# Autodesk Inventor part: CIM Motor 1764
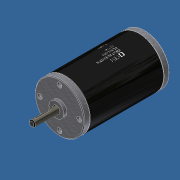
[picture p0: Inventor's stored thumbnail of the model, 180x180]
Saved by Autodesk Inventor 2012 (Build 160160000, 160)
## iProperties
Created: 2008-01
Part Number: CIM Motor 1764
Document SubType Name: Modeling
Designer: gstuder
Density: 1 g/cm^3
Mass: 1474.17 g
Surface Area: 428.563 cm^2
Volume: 334.464 cm^3
Catalog Web Link: ifirobotics.
Description: 2.5" CIM Motor
Material: Default
Author: gstuder
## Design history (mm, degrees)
sketch "Sketch1"
  geometry: L1 (0, 44.45)-(0, -44.45) reference; L2 (-44.45, 0)-(44.45, 0) reference; C1 r 31.75 at (0, 0)
  constraints: 2 midpoint, 1 centre point
  dimensions: "d0" = 63.5 diameter of C1
extrude "Extrusion1" new body sketch "Sketch1" stored distance "d1" = 95.25; taper "d2" = 0 deg
fillet "Fillet1" dims "d3" = 0.635
sketch "Sketch2"
  geometry: C1 r 31.75 at (0, 0) reference; C2 r 31.75 at (0, 0) reference
extrude "Extrusion3" join sketch "Sketch2" distance "d7" = 7.2898; taper "d8" = 0 deg
mirror "Mirror1"
chamfer "Chamfer1" distance "d9" = 0.889; stored, may be unused: second distance "d10" = 3.175, angle "d11" = 45 deg
sketch "Sketch3"
  geometry: L1 (-15.579, -19.05)-(-15.579, 13.97); L2 (-15.579, 13.97)-(16.51, 13.97); L3 (16.51, 13.97)-(16.51, -19.05); L4 (16.51, -19.05)-(-15.579, -19.05); L5 (-31.75, -46.99)-(31.75, -46.99) reference; L6 (31.75, 46.99)-(-31.75, 46.99) reference; 1 other entity
  constraints: 2 perpendicular, 2 other
  dimensions: "d21" = 33.02 distance between parallel lines of L6 L2; "d22" = 27.94 distance between parallel lines of L5 L4; "d27" = 15.24 distance from line of L3 L6.start
feature "Decal1" sketch "Sketch3"
sketch "Sketch4"
  geometry: C1 r 30.861 at (0, 0) reference; C2 r 9.525 at (0, 0)
  constraints: 1 centre point, 1 coincident
  dimensions: "d28" = 19.05 diameter of C2
extrude "Extrusion4" join sketch "Sketch4" distance "d29" = 4.064; taper "d30" = 0 deg
sketch "Sketch5"
  geometry: C1 r 9.525 at (0, 0) reference; C2 r 4.763 at (0, 0)
  constraints: 1 centre point, 1 coincident
  dimensions: "d31" = 9.525 diameter of C2
extrude "Extrusion5" cut sketch "Sketch5" distance "d32" = 101.6; taper "d33" = 0 deg
sketch "Sketch6"
  geometry: C1 r 4.763 at (0, 0) reference; C2 r 3.969 at (0, 0)
  constraints: 1 centre point, 1 coincident
  dimensions: "d35" = 7.9375 diameter of C2
extrude "Extrusion6" join sketch "Sketch6" distance "d36" = 133.223; taper "d37" = 0 deg
chamfer "Chamfer2" distance "d39" = 1.016; stored, may be unused: second distance "d40" = 3.175, angle "d41" = 45 deg
workplane "Work Plane1"
sketch "Sketch7"
  geometry: L1 (0, -41.397)-(0, 162.326) reference; L2 (-0.953, 128.524)-(-0.952, 110.299); L3 (0.953, 110.299)-(0.953, 128.524); L4 (-2.953, 133.223)-(2.953, 133.223) reference; A1 r 0.953 centre (0, 110.299) between (-0.952, 110.299) and (0.953, 110.299); A2 r 0.953 centre (0, 128.524) between (0.953, 128.524) and (-0.953, 128.524)
  constraints: 4 end point, 4 point on circle, 2 centre point, 2 horizontal alignment, 2 point on line, 2 tangent
  dimensions: "d42" = 180 deg dimension on A1.centre L3.start L2.end; "d43" = 1.905 distance of L3.start L2.end; "d44" = 180 deg dimension on A2.centre L3.end L2.start; "d45" = 20.1295 dimension on A1 A2; "d46" = 4.699 distance from line of L4 A2.centre
extrude "Extrusion7" cut sketch "Sketch7" distance "d47" = 1.27; taper "d48" = 0 deg
sketch "Sketch8"
  geometry: C1 r 30.861 at (0, 0) reference; C2 r 14.935 at (0, 0)
  constraints: 1 centre point, 1 coincident
  dimensions: "d49" = 29.8704 diameter of C2
extrude "Extrusion8" join sketch "Sketch8" distance "d50" = 4.6101; taper "d51" = 0 deg
fillet "Fillet2" dims "d52" = 0.3175
chamfer "Chamfer3" distance "d53" = 1.905; stored, may be unused: second distance "d54" = 3.175, angle "d55" = 45 deg
sketch "Sketch9"
  geometry: L1 (-44.45, 0)-(44.45, 0) reference; L2 (0, 44.45)-(0, -44.45) reference; C1 r 30.861 at (0, 0) reference; C2 r 9.525 at (0, 0) reference; C3 r 30.861 at (0, 0) reference; 4 further points
  constraints: 1 point on line, 5 other
  dimensions: "d56" = 25.4 distance of C1.centre point (0, 25.4); "d59" = 360 deg dimension on C1.centre point (0, 25.4) (derived)
hole "Hole1" sketch "Sketch9" at (0, 25.4), (-25.4, 0), (0, -25.4), (25.4, 0) diameter "d61" = 3.302; stored, may be unused: countersink angle "d65" = 82 deg, drill point angle "d67" = 0 deg; dims "d62" = 12.7, "d63" = 6.35, "d64" = 6.35, "d66" = 12.7
sketch "Sketch10"
  geometry: C1 r 1.651 at (-25.4, -25.4) reference; C2 r 1.651 at (0, -50.8) reference; C3 r 1.651 at (25.4, -25.4) reference
extrude "Extrusion9" join sketch "Sketch10" distance "d68" = 10.795; taper "d69" = 0 deg
workplane "Work Plane3"
  workaxis "Work Axis1"
  workplane "Work Plane2"
sketch "Sketch11"
  geometry: C1 r 30.861 at (0, 0) reference; C2 r 15.253 at (0, 0) reference
sketch "Sketch12"
  geometry: C1 r 30.861 at (0, 0) reference; C2 r 5.131 at (25.235, 0); C3 r 5.131 at (-25.235, 0)
  constraints: 2 centre point
  dimensions: "d82" = 10.2616 diameter of C3; "d83" = 10.2616 diameter of C2; "d84" = 0 vertical distance of C1.centre C2.centre; "d85" = 0 vertical distance of C3.centre C2.centre; "d86" = 50.4698 distance of C3.centre C2.centre; "d87" = 25.2349 distance of C1.centre C2.centre
extrude "Extrusion10" cut sketch "Sketch12" distance "d88" = 104.775; taper "d89" = 0 deg
sketch "Sketch13"
  geometry: C1 r 5.131 at (-25.235, 0) reference; C2 r 5.131 at (25.235, 0) reference; C3 r 5.131 at (-25.235, 0); C4 r 5.131 at (25.235, 0)
  constraints: 2 centre point, 2 coincident, 2 concentric
extrude "Extrusion11" join sketch "Sketch13" distance "d90" = 9.525; taper "d91" = 0 deg
sketch "Sketch14"
  geometry: C1 r 30.861 at (0, 0) reference; C2 r 5.131 at (25.235, 0); C3 r 5.131 at (-25.235, 0)
  constraints: 2 centre point, 5 other
  dimensions: "d92" = 10.2616 diameter of C2; "d93" = 0 vertical distance of C1.centre C2.centre; "d94" = 25.2349 distance of C1.centre C2.centre; "d97" = 360 deg dimension on C1.centre C2.centre (derived)
extrude "Extrusion12" cut sketch "Sketch14" distance "d99" = 6.35; taper "d100" = 0 deg
sketch "Sketch15"
  geometry: C1 r 5.131 at (0, 0) reference; C2 r 1.587 at (0, 0); C3 r 1.587 at (50.47, 0)
  constraints: 2 centre point, 1 coincident
  dimensions: "d101" = 50.4698 distance of C2.centre C3.centre; "d102" = 3.175 diameter of C3; "d103" = 3.175 diameter of C2
extrude "Extrusion13" cut sketch "Sketch15" distance "d104" = 98.425; taper "d105" = 0 deg
sketch "Sketch16"
  geometry: C1 r 5.131 at (-25.235, 0) reference; C2 r 3.988 at (-18.834, -10.389); C3 r 3.988 at (-13.246, -16.739)
  constraints: 2 centre point
  dimensions: "d106" = 10.3886 vertical distance of C1.centre C2.centre; "d107" = 6.35 vertical distance of C2.centre C3.centre; "d108" = 5.588 horizontal distance of C3.centre C2.centre; "d109" = 6.4008 horizontal distance of C1.centre C2.centre; "d110" = 7.9756 diameter of C2; "d111" = 7.9756 diameter of C3
extrude "Extrusion14" join sketch "Sketch16" distance "d112" = 2.4384; taper "d113" = 0 deg
sketch "Sketch17"
  geometry: C1 r 3.988 at (0, 0) reference; C2 r 1.829 at (0, 0); C3 r 3.988 at (5.588, -6.35) reference; C4 r 3.988 at (5.588, -6.35) reference; C5 r 3.988 at (5.588, -6.35) reference; C6 r 1.829 at (5.588, -6.35)
  constraints: 2 centre point, 2 coincident, 1 equal radius
  dimensions: "d114" = 3.6576 diameter of C2
extrude "Extrusion15" cut sketch "Sketch17" distance "d115" = 3.175; taper "d116" = 0 deg
chamfer "Chamfer4" distance "d117" = 2.159; stored, may be unused: second distance "d118" = 3.175, angle "d119" = 45 deg
workplane "Work Plane4"
  workaxis "Work Axis2"
  workaxis "Work Axis3"
sketch "Sketch18"
  geometry: L1 (0, 5.131)-(0, -5.131) reference; L2 (-6.35, 5.131)-(0, 5.131) reference; L3 (-6.35, -5.131)-(0, -5.131) reference; L4 (0, -5.131)-(-0.101, -5.131); L5 (-3.454, -1.727)-(-3.454, 0); L6 (-3.454, 5.131)-(0, 5.131); L7 (0, 5.131)-(0, -5.131); L8 (-3.454, -1.727)-(-3.454, 1.727); L9 (-3.454, 0)-(0, 0); L10 (-40.985, 0)-(169.192, 0) reference; A1 r 3.404 centre (-0.05, -1.727) between (-3.454, -1.727) and (0, -5.131); A2 r 3.404 centre (-0.05, 1.727) between (0, 5.131) and (-0.101, 5.131)
  constraints: 12 end point, 5 point on circle, 2 centre point, 2 midpoint, 2 parallel, 2 point on line, 2 tangent, 1 horizontal, 1 perpendicular
  dimensions: "d120" = 3.4544 distance between parallel lines of L5 L7; "d121" = 3.4544 distance of L5.start L8.end; "d122" = 3.4036 distance of L6.start L8.end
revolve "Revolution1" sketch "Sketch18" stored, may be unused: angle "d123" = 90 deg
sketch "Sketch19"
  geometry: L1 (-0.953, 3.175)-(0.952, 3.175); L2 (0.952, 3.175)-(0.953, -3.175); L3 (0.953, -3.175)-(-0.952, -3.175); L4 (-0.952, -3.175)-(-0.953, 3.175); L5 (-3.175, 0.953)-(3.175, 0.953); L6 (3.175, 0.953)-(3.175, -0.952); L7 (3.175, -0.952)-(-3.175, -0.953); L8 (-3.175, -0.953)-(-3.175, 0.953); C1 r 1.727 at (0, 0) reference
  constraints: 16 end point, 4 parallel, 2 horizontal, 2 perpendicular
  dimensions: "d124" = 1.905 distance between parallel lines of L7 L5; "d125" = 1.905 distance between parallel lines of L4 L2; "d126" = 0.9525 distance from line of C1.centre L5; "d127" = 0.9525 distance from line of C1.centre L2; "d128" = 3.175 distance from line of C1.centre L1; "d129" = 3.175 distance from line of L3 C1.centre; "d130" = 3.175 distance from line of L8 C1.centre; "d131" = 3.175 distance from line of L6 C1.centre
extrude "Extrusion16" cut sketch "Sketch19" distance "d132" = 2.54; taper "d133" = -32 deg
pattern_circular "Circular Pattern1" dims angle "d135" = 360 deg
sketch "Sketch20"
  geometry: C1 r 1.829 at (0, 0) reference
node "3"
node "1"
body "Solid1"
node "Projected Loop1"
node "Image1"
node "Projected Loop2"
node "Projected Loop3"
node "Projected Loop4"
node "Projected Loop5"
node "Projected Loop6"
node "Projected Loop7"
node "Projected Loop8"
other parameters: "d71" = 90 deg
